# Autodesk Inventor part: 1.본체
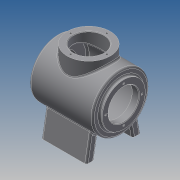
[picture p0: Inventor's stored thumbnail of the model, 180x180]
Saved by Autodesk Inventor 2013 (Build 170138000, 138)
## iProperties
Created: 2015-01
Part Number: 1.본체
Material: Generic
Document SubType Name: Modeling
Designer: kb543-154
Density: 1 g/cm^3
Author: kb543-154
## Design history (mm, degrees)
sketch "스케치1"
  geometry: L1 (-61, 0)-(-61, 38); L2 (-61, 38)-(-56, 38); L3 (-56, 38)-(-56, 50); L4 (-56, 50)-(56, 50); L5 (56, 50)-(56, 38); L6 (56, 38)-(61, 38); L7 (61, 38)-(61, 0); L8 (61, 0)-(-61, 0); 2 further points
  constraints: 16 end point, 5 parallel, 1 coincident, 1 collinear, 1 midpoint, 1 perpendicular, 1 vertical
  dimensions: "d0" = 76 diameter of L2 L8; "d2" = 100 diameter of L4 L8; "d3" = 76 diameter of L6 L8; "d4" = 112 distance of L3.end L4.end; "d5" = 122 distance of L7.end L1.start; "d6" = 5 distance of L1.end L2.end
revolve "회전1" sketch "스케치1" stored, may be unused: angle "d7" = 90 deg
sketch "스케치2"
  geometry: L1 (-61, -38)-(-61, 38) reference; L2 (61, -38)-(61, 38) reference; L3 (-61, 0)-(61, 0); L4 (-61, 27)-(-49, 27); L5 (-56, -50)-(-56, 50) reference; L6 (-49, 27)-(-49, 45); L7 (-49, 45)-(48, 45); L8 (48, 45)-(48, 27); L9 (48, 27)-(61, 27); L10 (56, -50)-(56, 50) reference; 1 further point
  constraints: 12 end point, 3 perpendicular, 2 midpoint, 2 point on line, 1 collinear, 1 parallel, 1 vertical
  dimensions: "d8" = 54 diameter of L4 L3; "d10" = 90 diameter of L7 L3; "d11" = 97 distance between parallel lines of L8 L6; "d12" = 7 horizontal distance of L6.end L5.end
revolve "회전2" sketch "스케치2" stored, may be unused: angle "d13" = 90 deg
sketch "스케치3"
  geometry: L1 (-36.887, -33.755)-(-45.041, -80); L2 (-45.041, -80)-(-31.041, -80); L3 (-31.041, -80)-(-24.609, -43.524); L4 (29.917, -40.062)-(36.959, -80); L5 (36.959, -80)-(50.959, -80); L6 (50.959, -80)-(41.714, -27.567); L7 (0, 50)-(0, -50); L8 (-47.944, 0)-(50, 0); 5 further points
  constraints: 16 end point, 3 midpoint, 2 collinear, 2 perpendicular, 1 coincident, 1 horizontal, 1 parallel, 8 other
  dimensions: "d24" = 80 distance from line of L2 point (0, 0); "d25" = 14 distance of L1.end L2.end; "d26" = 14 distance of L4.end L5.end; "d27" = 96 distance of L5.end L1.end; "d28" = 80 deg angle of L5 L4; "d29" = 100 deg angle of L5 L6; "d30" = 80 deg angle of L2 L3; "d31" = 100 deg angle of L1 L2 (derived); "d32" = 80 distance between parallel lines of L8 L5; "d33" = 36.29295 distance from line of point (0, 0) L6; "d34" = 69.72143 distance from line of L8.start L4
extrude "돌출1" join sketch "스케치3" stored distance "d35" = 80; taper "d36" = 0 deg
node "작업 평면2"
sketch "스케치7"
  geometry: L1 (21, -12.959)-(21, -88.959) reference; C1 r 38 at (-41, -50.959); 2 further points
  constraints: 1 centre point, 1 horizontal alignment, 1 midpoint
  dimensions: "d39" = 76 diameter of C1; "d41" = 62 distance from line of C1.centre L1
extrude "돌출2" join sketch "스케치7" stored distance "d42" = 80; taper "d43" = 0 deg
hole "구멍1" diameter "d46" = 54; stored, may be unused: countersink angle "d50" = 90 deg, drill point angle "d52" = 118 deg; dims "d44" = 10, "d45" = 10, "d47" = 6, "d48" = 4, "d49" = 2, "d51" = 8
sketch "스케치9"
  geometry: C1 r 27 at (0, 0) reference; 5 further points
  constraints: 1 vertical alignment, 5 other
  dimensions: "d53" = 32 distance of C1.centre point (0, 32); "d56" = 360 deg dimension on C1.centre point (0, 32) (derived)
hole "구멍2" sketch "스케치9" at (-32, 0), (0, -32), (32, 0), (0, 32) diameter "d58" = 3.242; stored, may be unused: countersink angle "d62" = 90 deg, drill point angle "d64" = 118 deg; dims "d59" = 8, "d60" = 4, "d61" = 2, "d63" = 10
sketch "스케치10"
  geometry: C1 r 27 at (0, 0) reference; 4 further points
  constraints: 1 vertical alignment, 5 other
  dimensions: "d65" = 32 distance of C1.centre point (0, 32); "d68" = 360 deg dimension on C1.centre point (0, 32) (derived)
hole "구멍3" sketch "스케치10" at (0, -32), (32, 0), (0, 32), (-32, 0) diameter "d70" = 3.242; stored, may be unused: countersink angle "d74" = 90 deg, drill point angle "d76" = 118 deg; dims "d71" = 8, "d72" = 4, "d73" = 2, "d75" = 10
node "작업 평면4"
  node "작업 평면3"
sketch "스케치13"
  geometry: L1 (-26, 6)-(28, 6); L2 (28, 6)-(28, -6); L3 (28, -6)-(-26, -6); L4 (-26, -6)-(-26, 6); L5 (-61, -38)-(-61, 38) reference; L6 (-37, 62)-(39, 62) reference; L7 (1, 6)-(1, -6); 3 further points
  constraints: 10 end point, 4 midpoint, 2 parallel, 1 horizontal, 1 horizontal alignment, 1 perpendicular
  dimensions: "d82" = 54 distance of L1.start L1.end; "d84" = 12 distance of L3.end L1.start; "d85" = 62 distance between parallel lines of L7 L5
extrude "돌출3" join sketch "스케치13" stored distance "d86" = 80; taper "d87" = 0 deg
sketch "스케치14"
  geometry: L1 (26, -6)-(-28, -6) reference; L2 (26, 6)-(26, -6) reference; 4 further points
  constraints: 2 midpoint, 1 horizontal alignment, 1 vertical alignment, 1 other
feature "엠보싱1" sketch "스케치14" dims "d88" = 0.5, "d89" = 0
fillet "모깎기1" dims "d90" = 3
fillet "모깎기2" dims "d91" = 3
chamfer "모따기1" distance "d92" = 1; stored, may be unused: second distance "d93" = 2, angle "d94" = 45 deg
node "솔리드1"
mirror "대칭1"
other parameters: "d38" = -142, "d81" = 2
